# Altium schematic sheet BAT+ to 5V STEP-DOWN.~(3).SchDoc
size A3; SheetNumber: 11; SheetTotal: 12
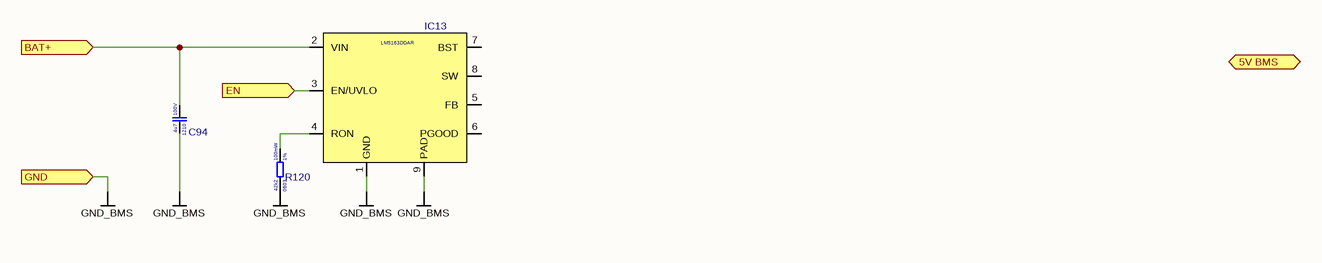
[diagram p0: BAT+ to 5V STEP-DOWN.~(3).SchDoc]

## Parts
C94  Voltage Rating: 100V  Case Code (Imperial): 1210  Capacitance: 4u7  [CAP_1210]  (hidden comment: HMK325C7475KN-TE)
IC13  LM5163DDAR  [ESOP-8]
R120  Resistance Tolerance: 1%  Resistance: 42k2  Power Rating: 100mW  Case Code (Imperial): 0603  [RES_0603]  (hidden comment: 0603WAF4222T5E)

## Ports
5V BMS (bidir, see BMS[4B], MCU[1B]), BAT+ (in, see BMS[4B], BMS[1A], BQ76952 BMS[1A]), EN (in, see BMS[4B]), GND (in, see BMS[4B], BQ76952 BMS[1D], MCU[1C])

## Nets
GND_BMS: C94.1 IC13.1(GND) IC13.9(PAD) R120.1 ; port GND
BAT+: C94.2 IC13.2(VIN) ; port BAT+
EN: IC13.3(EN/UVLO) ; port EN
NetIC13_4: IC13.4(RON) R120.2

Not connected (* = marked no-connect by the designer): IC13 5(FB) 6(PGOOD) 7(BST) 8(SW)

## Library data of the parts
C94 = HMK325C7475KN-TE: Cap 4.7uF 100V 1210 X7R; Manufacturer: Taiyo Yuden
IC13 = LM5163DDAR: DCDC Step-down Converter 9~100Vin 0.5Aout; Manufacturer: Texas Instruments
R120 = 0603WAF4222T5E: Res 42k2 0603 1% 100mW 75V; Manufacturer: Uni-Royal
